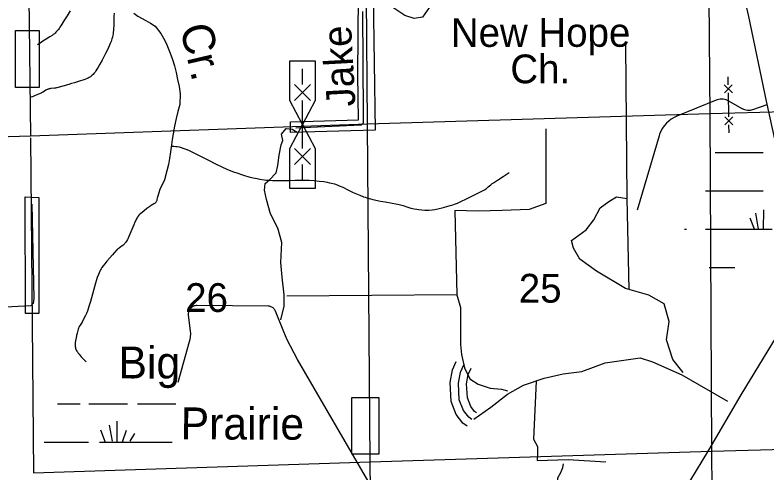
# Model space of a CAD drawing. Extents: x 2480962 to 2688785, y 277103 to 599240.
# Drawn here: x 2538319 to 2550088, y 469792 to 476959 of the extents above; entities that cross this region are included whole.
import ezdxf

# ---------------------------------------------------------------- set-up
doc = ezdxf.new("R2010")
doc.units = 0
for name, color, linetype in [('County Routes Highway Center Lines', 7, 'Continuous'), ('Culture Text', 7, 'Continuous'), ('Lakes and Ponds Text', 7, 'Continuous'), ('Level 31', 7, 'Continuous'), ('Local Roads Improved', 7, 'Continuous'), ('Local Roads Paved', 7, 'Continuous'), ('Local Roads Related Cells', 7, 'Continuous'), ('Local Roads Related Text', 7, 'Continuous'), ('Narrow River Creek and Branch and Slough', 7, 'Continuous'), ('Railroads Text', 7, 'Continuous'), ('Section Lines', 7, 'Continuous'), ('Section Numbers', 7, 'Continuous'), ('Swamps', 7, 'Continuous'), ('Swamps Text', 7, 'Continuous'), ('Township and Range lines', 7, 'Continuous'), ('Uninventoried Roads and Features', 7, 'Continuous')]:
    doc.layers.add(name, color=color, linetype=linetype)

msp = doc.modelspace()

# ---------------------------------------------------------------- linework, layer by layer
at = {"layer": 'County Routes Highway Center Lines'}
for points in [[(2549189.804, 479565.022), (2549799.145, 476936.151), (2550077.701, 475613.011), (2550216.979, 474968.85)], [(2550234.389, 471922.145), (2549677.277, 471016.839), (2549172.395, 470146.352), (2548876.429, 469658.879), (2548597.873, 469136.586), (2548354.137, 468335.738), (2548110.4, 467517.48), (2547831.844, 466438.076), (2547675.157, 466002.833), (2547414.011, 465289.033), (2547065.816, 464610.053), (2546891.718, 464244.449), (2546769.85, 463617.698), (2546526.114, 462242.328), (2546404.245, 461563.348), (2546038.641, 460431.715), (2545812.314, 459822.374)]]:
    msp.add_lwpolyline(points, dxfattribs=at)
at = {"layer": 'Level 31'}
for points in [[(2543695.994, 477268.214), (2543922.353, 477268.214), (2543957.564, 475155.53), (2542629.592, 475120.318), (2542629.592, 475286.315), (2543695.994, 475316.496), (2543685.934, 476020.724)], [(2538327.377, 476716.287), (2538697.869, 476716.287), (2538697.869, 475826.379), (2538327.377, 475826.379)], [(2538475.126, 474112.362), (2538691.185, 474102.541), (2538691.185, 472285.681), (2538484.947, 472285.681)], [(2543592.162, 470975.176), (2544013.977, 470975.176), (2544013.977, 470083.383), (2543592.162, 470083.383)]]:
    msp.add_lwpolyline(points, close=True, dxfattribs=at)
at = {"layer": 'Local Roads Improved'}
msp.add_lwpolyline([(2538584.242, 473998.2), (2538610.612, 472521.518), (2538604.019, 472442.41), (2538564.465, 472409.448), (2538267.811, 472389.671), (2537582.208, 472363.302)], dxfattribs=at)
at = {"layer": 'Local Roads Paved'}
for points in [[(2544808.351, 477083.034), (2544697.66, 476928.067), (2544564.831, 476905.929), (2544420.933, 476950.205), (2544155.276, 477127.31)], [(2543756.789, 477016.62), (2543767.859, 475400.536), (2543767.859, 475267.707), (2543734.651, 475234.5), (2542716.297, 475190.224)]]:
    msp.add_lwpolyline(points, dxfattribs=at)
at = {"layer": 'Local Roads Related Cells'}
for p, q in [((2542618.273, 475619.193), (2542618.273, 476244.193)), ((2542618.273, 476244.193), (2543018.273, 476244.193)), ((2543018.273, 476244.193), (2543018.273, 475619.193)), ((2542818.272, 475869.193), (2542818.272, 476119.193)), ((2542693.272, 475869.193), (2542943.272, 475619.193)), ((2542693.272, 475619.193), (2542943.272, 475869.193)), ((2542818.272, 475244.194), (2542618.273, 475619.193)), ((2543018.273, 475619.193), (2542818.272, 475244.194)), ((2542818.272, 474869.195), (2542818.272, 475619.193)), ((2542618.273, 474869.195), (2542818.272, 475244.194)), ((2542818.272, 475244.194), (2543018.273, 474869.195)), ((2542618.273, 474244.195), (2542618.273, 474869.195)), ((2542693.272, 474869.195), (2542943.272, 474619.195)), ((2542695.581, 474619.195), (2542945.581, 474869.195)), ((2543018.273, 474869.195), (2543018.273, 474244.195)), ((2542818.272, 474369.195), (2542818.272, 474619.195)), ((2543018.273, 474244.195), (2542618.273, 474244.195))]:
    msp.add_line(p, q, dxfattribs=at)
at = {"layer": 'Narrow River Creek and Branch and Slough'}
for points in [[(2539182.124, 477022.173), (2539133.029, 476944.747), (2539083.934, 476867.32), (2539034.839, 476789.893), (2539020.986, 476768.635), (2539008.287, 476750.265), (2538996.689, 476734.484), (2538986.136, 476720.978), (2538976.573, 476709.444), (2538959.045, 476690.028), (2538945.194, 476676.225), (2538934.381, 476666.363), (2538917.445, 476652.456), (2538899.6, 476639.732), (2538863.104, 476616.269), (2538807.923, 476582.059), (2538752.976, 476547.531), (2538711.052, 476520.5), (2538669.212, 476493.335)], [(2539871.998, 476990.087), (2539867.518, 476935.36), (2539865.088, 476898.985), (2539863.448, 476835.155), (2539862.846, 476787.251), (2539861.878, 476751.368), (2539860.493, 476724.509), (2539856.807, 476684.345), (2539854.029, 476664.335), (2539850.5, 476644.381), (2539843.686, 476614.482), (2539836.434, 476588.749), (2539829.22, 476566.522), (2539822.316, 476547.267), (2539809.106, 476513.939), (2539798.427, 476489.192), (2539781.503, 476452.357), (2539763.92, 476415.715), (2539735.563, 476358.819), (2539713.709, 476316.756), (2539680.086, 476254.221), (2539645.573, 476191.828), (2539620.046, 476145.156), (2539600.493, 476110.659), (2539584.764, 476085.433), (2539572.018, 476067.03), (2539561.778, 476053.584), (2539553.65, 476043.724), (2539540.647, 476029.342), (2539526.554, 476015.498), (2539516.536, 476006.735), (2539506.872, 475999.114), (2539497.592, 475992.457), (2539479.666, 475981.139), (2539463.483, 475972.345), (2539448.998, 475965.385), (2539436.111, 475959.781), (2539413.174, 475950.874), (2539378.156, 475939.024), (2539342.881, 475927.989), (2539250.976, 475899.521), (2539204.944, 475885.652), (2539158.76, 475872.186), (2539066.745, 475846.503), (2538974.565, 475821.669), (2538966.136, 475819.609), (2538950.15, 475816.56), (2538936.017, 475814.542), (2538886.222, 475808.942), (2538873.863, 475807.134), (2538864.659, 475805.482), (2538850.992, 475802.378), (2538837.533, 475798.332), (2538830.169, 475795.597), (2538823.406, 475792.739), (2538811.036, 475786.731), (2538800.475, 475780.925), (2538782.364, 475769.986), (2538755.363, 475753.234), (2538741.594, 475745.423), (2538734.572, 475741.803), (2538727.433, 475738.43), (2538688.512, 475720.972), (2538659.219, 475708.079), (2538614.904, 475689.522), (2538592.497, 475680.772), (2538569.872, 475672.48)], [(2540178.482, 476987.907), (2540242.537, 476941.363), (2540364.993, 476874.61), (2540440.449, 476832.897), (2540514.157, 476787.142), (2540600.313, 476672.239), (2540642.918, 476597.145), (2540681.709, 476520.26), (2540715.956, 476442.074), (2540747.334, 476362.743), (2540782.495, 476263.509), (2540813.556, 476162.951), (2540840.249, 476058.049), (2540864.082, 475952.336), (2540886.884, 475839.272), (2540904.268, 475725.7), (2540896.096, 475556.43), (2540868.573, 475447.496), (2540841.057, 475338.841), (2540814.022, 475219.949), (2540791.6, 475100.199), (2540779.565, 475012.802), (2540767.656, 474925.392), (2540753.655, 474819.412), (2540738.953, 474713.509), (2540718.566, 474617.611), (2540694.105, 474522.51), (2540659.149, 474379.24), (2540587.293, 474230.094), (2540546.756, 474107.877)], [(2540765.232, 474907.497), (2540804.352, 474906.068), (2540833.682, 474903.55), (2540855.662, 474900.658), (2540888.586, 474894.427), (2540921.43, 474885.568), (2540961.525, 474872.32), (2540990.75, 474861.694), (2541033.549, 474844.273), (2541075.503, 474824.607), (2541211.207, 474755.329), (2541346.899, 474686.24), (2541455.744, 474632.101), (2541565.028, 474578.734), (2541623.656, 474551.969), (2541668.218, 474533.325), (2541735.829, 474507.07), (2541804.136, 474482.136), (2541864.351, 474461.796), (2541909.818, 474447.923), (2541978.591, 474429.029), (2542048.151, 474412.043), (2542107.346, 474399.157), (2542151.848, 474390.697), (2542218.892, 474380.408), (2542252.591, 474376.518), (2542286.437, 474373.572), (2542349.856, 474369.857), (2542444.997, 474367.122), (2542540.119, 474367.061), (2542604.806, 474368.821), (2542701.834, 474373.446), (2542750.348, 474375.444), (2542798.86, 474376.488), (2542868.967, 474375.558), (2542921.517, 474373.149), (2543000.313, 474367.392), (2543079.102, 474359.831), (2543150.528, 474351.336), (2543203.742, 474342.985), (2543243.351, 474335.174), (2543272.844, 474328.265), (2543316.678, 474315.933), (2543359.942, 474300.899), (2543392.218, 474287.707), (2543447.222, 474262.271), (2543528.081, 474221.723), (2543568.669, 474201.905), (2543609.912, 474183.332), (2543717.626, 474137.216), (2543772.136, 474115.747), (2543799.771, 474105.944), (2543827.742, 474096.963), (2543880.304, 474082.385), (2543919.986, 474072.797), (2544039.767, 474047.501), (2544112.532, 474033.652), (2544222.023, 474014.73), (2544276.67, 474004.881), (2544331.096, 473994.022), (2544353.951, 473988.541), (2544393.259, 473976.797), (2544451.751, 473956.908), (2544481.341, 473947.305), (2544511.503, 473938.769), (2544567.004, 473925.843), (2544608.686, 473917.928), (2544639.968, 473913.117), (2544686.914, 473907.904), (2544733.868, 473905.329), (2544767.458, 473905.269), (2544796.873, 473906.441), (2544848.379, 473911.045), (2544887.015, 473916.466), (2544915.987, 473921.542), (2544959.418, 473930.642), (2545002.8, 473941.346), (2545076.063, 473961.11), (2545130.027, 473976.84), (2545169.941, 473989.592), (2545199.557, 473999.884), (2545243.468, 474016.769), (2545286.755, 474035.745), (2545394.606, 474087.23), (2545501.895, 474139.615), (2545583.551, 474179.869), (2545664.514, 474221.501), (2545683.772, 474233.206), (2545699.639, 474244.906), (2545725.954, 474267.553), (2545764.424, 474303.068), (2545784.386, 474319.79), (2545805.558, 474334.756), (2545837.026, 474353.688), (2545868.418, 474372.761), (2545960.44, 474431.727), (2546051.643, 474491.977)], [(2540546.756, 474107.877), (2540544.287, 474098.58), (2540538.828, 474065.044), (2540537.013, 474056.796), (2540532.986, 474044.825), (2540530.166, 474039.088), (2540526.674, 474033.558), (2540521.82, 474027.307), (2540511.74, 474016.919), (2540502.053, 474009.01), (2540493.064, 474002.79), (2540476.569, 473992.952), (2540451.27, 473978.978), (2540438.975, 473971.523), (2540427.288, 473963.254), (2540382.772, 473928.402), (2540338.467, 473893.12), (2540281.723, 473849.044), (2540268.291, 473837.261), (2540258.757, 473827.927), (2540245.604, 473812.889), (2540239.649, 473804.814), (2540234.173, 473796.311), (2540225.752, 473781.481), (2540212.507, 473755.029), (2540194.864, 473714.572), (2540177.79, 473673.84), (2540147.12, 473601.994), (2540116.425, 473530.147), (2540100.681, 473494.418), (2540088.287, 473467.918), (2540078.431, 473448.313), (2540062.394, 473419.493), (2540053.679, 473405.405), (2540044.42, 473391.57), (2540037.985, 473383.072), (2540031.454, 473375.616), (2540018.105, 473362.766), (2540005.489, 473352.48), (2539982.083, 473335.834), (2539946.352, 473311.48), (2539929.423, 473298.332), (2539921.437, 473291.264), (2539913.865, 473283.768), (2539873.676, 473240.804), (2539844.024, 473208.132), (2539800.395, 473158.186), (2539757.873, 473106.848), (2539722.854, 473063.766), (2539697.178, 473031.125), (2539678.913, 473006.057), (2539666.053, 472986.756), (2539656.997, 472971.928), (2539644.536, 472949.011), (2539633.646, 472925.151), (2539623.04, 472898.336), (2539606.106, 472851.057), (2539594.488, 472815.348), (2539578.254, 472761.465), (2539562.762, 472707.307), (2539530.126, 472590.484), (2539497.384, 472473.696), (2539475.699, 472399.059), (2539464.209, 472361.923), (2539451.939, 472324.972), (2539444.176, 472304.173), (2539436.663, 472286.286), (2539422.252, 472255.537), (2539374.951, 472165.172), (2539367.513, 472151.682), (2539338.549, 472106.092), (2539324.712, 472082.909), (2539318.532, 472070.893), (2539313.062, 472058.47), (2539307.814, 472044.245), (2539300.255, 472018.995), (2539291.331, 471980.518), (2539283.014, 471941.707), (2539275.667, 471908.6), (2539265.89, 471858.874), (2539261.825, 471834.013), (2539258.472, 471809.174), (2539257.519, 471795.165), (2539257.826, 471782.907), (2539258.936, 471772.197), (2539262.686, 471753.524), (2539266.937, 471739.611), (2539270.894, 471729.245), (2539278.005, 471713.836), (2539286.451, 471698.625), (2539294.503, 471685.828), (2539309.038, 471665.209), (2539320.33, 471650.838), (2539337.934, 471630.263), (2539356.386, 471609.89), (2539393.209, 471570.134), (2539412.025, 471550.74), (2539431.454, 471531.808)]]:
    msp.add_lwpolyline(points, dxfattribs=at)
at = {"layer": 'Section Lines'}
for p, q in [((2543836.38, 475248.642), (2543797.854, 480599.415)), ((2538495.826, 480432.376), (2538559.138, 475064.037)), ((2549192.299, 475416.768), (2559805.122, 475712.924)), ((2549192.321, 475412.818), (2543836.38, 475248.643)), ((2543836.38, 475248.642), (2538560.675, 475064.088)), ((2543875.69, 469964.055), (2543836.382, 475248.643)), ((2538560.675, 475064.088), (2533286.709, 474891.598)), ((2538559.382, 475036.327), (2538605.621, 469791.667)), ((2549221.245, 470131.992), (2554543.75, 470285.388)), ((2543875.54, 469964.05), (2549221.245, 470131.992)), ((2538606.599, 469791.699), (2543875.54, 469964.05)), ((2543965.349, 464652.529), (2543875.69, 469964.055))]:
    msp.add_line(p, q, dxfattribs=at)
at = {"layer": 'Swamps'}
for p, q in [((2549277.079, 474806.108), (2549727.078, 474806.116)), ((2549727.078, 474806.116), (2550027.077, 474806.121)), ((2549127.088, 474206.107), (2549727.086, 474206.117)), ((2549727.086, 474206.117), (2550027.085, 474206.122)), ((2549955.095, 473606.186), (2549915.701, 473859.42)), ((2550033.257, 473606.143), (2550038.984, 473909.856)), ((2549892.773, 473607.108), (2549826.702, 473779.902)), ((2549127.096, 473606.109), (2549727.094, 473606.119)), ((2539471.601, 470875.162), (2540080.827, 470875.172)), ((2540236.683, 470872.556), (2540836.681, 470872.566)), ((2539790.346, 470540.978), (2539838.678, 470287.251)), ((2539911.168, 470601.39), (2539911.172, 470275.17)), ((2539657.442, 470468.482), (2539729.939, 470275.167)), ((2540056.156, 470456.406), (2539995.748, 470275.172)), ((2540189.061, 470408.079), (2540116.57, 470287.256)), ((2539639.856, 470275.166), (2540239.854, 470275.176))]:
    msp.add_line(p, q, dxfattribs=at)
for points in [[(2548798.7, 473606.104), (2548827.097, 473606.104)], [(2549727.094, 473606.119), (2550169.222, 473606.126)], [(2549181.093, 473006.111), (2549586.22, 473006.118)], [(2538981.352, 470872.536), (2539336.686, 470872.541)], [(2538775.118, 470275.152), (2539470.713, 470275.163)], [(2540239.854, 470275.176), (2540779.44, 470275.184)]]:
    msp.add_lwpolyline(points, dxfattribs=at)
at = {"layer": 'Township and Range lines'}
for p, q in [((2549152.324, 480741.243), (2549192.64, 475370.43)), ((2549192.299, 475416.768), (2549221.414, 470131.997)), ((2549221.264, 470150.934), (2549257.995, 464787.829))]:
    msp.add_line(p, q, dxfattribs=at)
at = {"layer": 'Uninventoried Roads and Features'}
for p, q in [((2549481.323, 475866.264), (2549478.94, 475991.241)), ((2549418.834, 475865.073), (2549546.194, 475742.478)), ((2549421.217, 475740.095), (2549543.812, 475867.455)), ((2549490.853, 475366.355), (2549483.705, 475741.287)), ((2549293.059, 475624.523), (2548679.048, 475376.511)), ((2549701.917, 475490.664), (2549493.298, 475610.67)), ((2550087.351, 475554.662), (2549862.802, 475475.798)), ((2549428.364, 475365.163), (2549555.724, 475242.568)), ((2549430.746, 475240.186), (2549553.341, 475367.546)), ((2549495.618, 475116.4), (2549493.235, 475241.377)), ((2548398.565, 475067.138), (2548057.516, 473907.369)), ((2542283.294, 472401.031), (2541165.833, 472411.611)), ((2542525.588, 472001.396), (2542396.131, 472323.951)), ((2541029.933, 472259.399), (2541059.914, 472016.036)), ((2541046.619, 471842.387), (2540867.863, 471209.806)), ((2543841.296, 469676.145), (2542738.403, 471566.322))]:
    msp.add_line(p, q, dxfattribs=at)
for points in [[(2547928.949, 472663.343), (2547902.365, 474087.829), (2547878.756, 476492.157)], [(2549493.298, 475610.67), (2549471.893, 475621.534), (2549449.469, 475630.101), (2549426.273, 475636.278), (2549402.558, 475639.994), (2549378.585, 475641.213), (2549354.615, 475639.918), (2549330.912, 475636.126), (2549307.736, 475629.877), (2549293.059, 475624.523)], [(2549862.802, 475475.798), (2549843.333, 475470.086), (2549823.373, 475466.441), (2549803.142, 475464.901), (2549782.861, 475465.485), (2549762.752, 475468.185), (2549743.036, 475472.972), (2549723.927, 475479.795), (2549705.637, 475488.578), (2549701.917, 475490.664)], [(2548679.048, 475376.511), (2548633.55, 475355.3), (2548590.52, 475329.45), (2548550.427, 475299.244), (2548513.712, 475265.012), (2548480.776, 475227.13), (2548451.979, 475186.013), (2548427.639, 475142.111), (2548408.021, 475095.905), (2548398.565, 475067.138)], [(2542480.25, 472187.473), (2542528.675, 472402.692), (2542531.911, 472578.259), (2542497.877, 472857.068), (2542480.456, 473088.064), (2542495.653, 473398.908), (2542432.26, 473621.088), (2542318.753, 473845.922), (2542253.289, 474073.838), (2542222.634, 474219.664), (2542231.58, 474322.087), (2542303.308, 474377.804), (2542406.367, 474488.268), (2542434.206, 474604.643), (2542455.148, 474765.206), (2542481.812, 474927.836), (2542510.876, 474996.028), (2542489.189, 475091.93), (2542560.036, 475182.338), (2542658.438, 475173.128), (2542732.762, 475126.699)], [(2546625.388, 475179.559), (2546624.345, 474008.966), (2546364.93, 473915.964), (2545943.742, 473902.006), (2545568.773, 473887.227), (2545200.763, 473901.543), (2545234.419, 472577.506), (2542574.723, 472560.001)], [(2548774.249, 471364.558), (2548617.086, 471565.204), (2548514.841, 471877.088), (2548559.627, 472159.716), (2548477.501, 472437.371), (2548239.139, 472576.288), (2547872.771, 472677.423), (2547419.277, 472950.029), (2547156.507, 473140.428), (2547057.887, 473309.695), (2547025.995, 473428.494), (2547260.416, 473596.105), (2547379.66, 473751.313), (2547478.836, 473938.822), (2547614.891, 474038.508), (2547734.27, 474112.724), (2547902.365, 474087.829)], [(2545234.419, 472577.506), (2545291.354, 472382.17), (2545289.183, 472088.994), (2545292.586, 471803.666), (2545308.194, 471643.978), (2545351.958, 471436.756), (2545435.189, 471267.12), (2545566.28, 471183.484), (2545756.564, 471118.623), (2545934.081, 471101.668), (2546025.13, 471078.781)], [(2541165.833, 472411.611), (2541151.649, 472411.003), (2541137.606, 472408.914), (2541123.859, 472405.37), (2541110.557, 472400.408), (2541097.847, 472394.083), (2541085.868, 472386.464), (2541074.751, 472377.633), (2541064.617, 472367.69), (2541055.579, 472356.742), (2541047.734, 472344.909), (2541041.17, 472332.321), (2541035.956, 472319.116), (2541032.152, 472305.438), (2541029.798, 472291.437), (2541028.921, 472277.267), (2541029.531, 472263.083), (2541029.933, 472259.399)], [(2542396.131, 472323.951), (2542390.724, 472335.617), (2542384.127, 472346.653), (2542376.413, 472356.94), (2542367.666, 472366.364), (2542357.981, 472374.821), (2542347.466, 472382.221), (2542336.234, 472388.48), (2542324.41, 472393.532), (2542312.122, 472397.32), (2542299.506, 472399.801), (2542286.7, 472400.952), (2542283.294, 472401.031)], [(2541059.914, 472016.036), (2541063.149, 471970.041), (2541061.558, 471923.96), (2541055.16, 471878.297), (2541046.619, 471842.387)], [(2542738.403, 471566.322), (2542579.768, 471874.16), (2542525.588, 472001.396)], [(2545501.273, 470636.174), (2545767.956, 470821.916), (2546024.627, 471022.845), (2546275.025, 471167.698), (2546603.302, 471277.779), (2546896.203, 471340.729), (2547189.741, 471378.624), (2547553.93, 471514.636), (2547847.322, 471558.313), (2548104.359, 471593.404), (2548294.546, 471532.398), (2548755.894, 471329.405), (2549468.96, 470916.463)], [(2545393.74, 470523.974), (2545329.207, 470570.66), (2545225.488, 470707.782), (2545145.598, 470909.507), (2545129.3, 471205.65), (2545167.062, 471407.9), (2545224.094, 471536.574)], [(2545468.766, 470627.68), (2545419.744, 470663.145), (2545338.081, 470771.108), (2545272.262, 470937.304), (2545257.953, 471197.302), (2545290.143, 471369.706), (2545341.115, 471484.707)], [(2545543.793, 470731.386), (2545510.28, 470755.631), (2545450.673, 470834.434), (2545398.925, 470965.101), (2545386.606, 471188.953), (2545413.223, 471331.512), (2545458.135, 471432.84)], [(2546477.466, 471230.406), (2546431.238, 470322.928), (2546493.861, 470206.794), (2546498.282, 470108.549), (2546491.702, 469988.828), (2546974.544, 470000.408), (2547568.261, 469966.436)], [(2547899.73, 467451.976), (2547621.264, 467578.36), (2547498.505, 467637.127), (2547468.878, 467742.481), (2547457.951, 467869.496), (2547420.14, 467993.939), (2547303.704, 468106.853), (2547154.605, 468444.612), (2547024.889, 468777.051), (2546879.7, 469188.185), (2546816.871, 469539.584), (2546812.463, 469713.039), (2546862.295, 469797.157), (2546893.038, 469875.033), (2546901.088, 469936.935)]]:
    msp.add_lwpolyline(points, dxfattribs=at)

# ---------------------------------------------------------------- texts
at = {"layer": 'Culture Text'}
for s, p in [('New Hope', (2545140.073, 476459.5)), ('Ch.', (2546071.846, 475890.585))]:
    msp.add_text(s, height=450, rotation=0.0515333, dxfattribs=at).set_placement(p)
at = {"layer": 'Lakes and Ponds Text'}
msp.add_text('Cr.', height=500, rotation=283.1348667, dxfattribs=at).set_placement((2540897.461, 476767.194))
at = {"layer": 'Local Roads Related Text'}
msp.add_text('Jake', height=450, rotation=93.1796528, dxfattribs=at).set_placement((2543648.479, 475535.667))
at = {"layer": 'Railroads Text'}
msp.add_text('G.S.&F. RY.', height=450, rotation=302.5339278, dxfattribs=at).set_placement((2537485.558, 469848.535))
at = {"layer": 'Section Numbers'}
for s, p in [('25', (2546203.8, 472457.839)), ('26', (2540981.975, 472312.041))]:
    msp.add_text(s, height=450, rotation=359.9794333, dxfattribs=at).set_placement(p)
at = {"layer": 'Swamps Text'}
for s, rotation, p in [('Big', 359.8350139, (2539936.629, 471270.746)), ('Prairie', 359.8350167, (2540910.475, 470317.177))]:
    msp.add_text(s, height=500, rotation=rotation, dxfattribs=at).set_placement(p)

doc.saveas('drawing.dxf')
